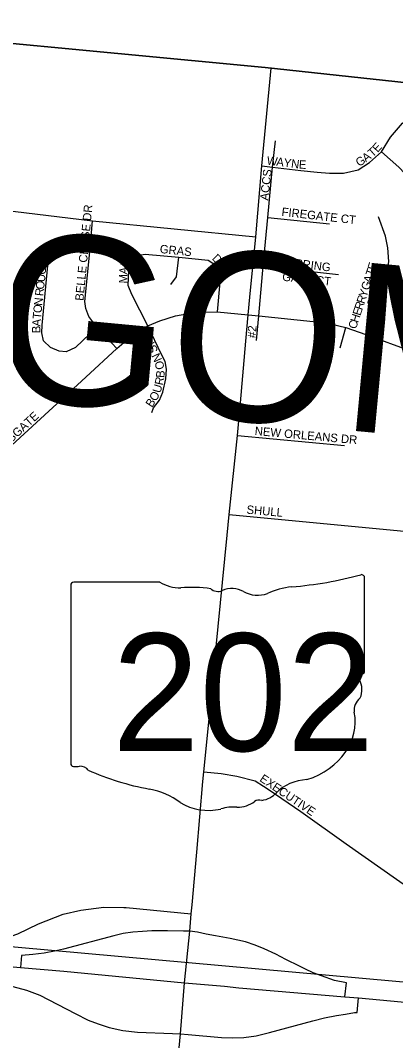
# Model space of a CAD drawing. Extents: x 0 to 680, y 0 to 440.
# Drawn here: x 66.7 to 73.29, y 260.23 to 278.15 of the extents above; entities that cross this region are included whole.
import ezdxf

# ---------------------------------------------------------------- set-up
doc = ezdxf.new("R2010")
doc.units = 0
for name, color, linetype in [('GM_X_Adjacent_County', 7, 'Continuous'), ('GM_X_Adjacent_County_Text', 7, 'Continuous'), ('GM_X_City_Street', 7, 'Continuous'), ('GM_X_City_Street_Text', 7, 'Continuous'), ('GM_X_County', 7, 'Continuous'), ('GM_X_Interchange_Ramps', 7, 'Continuous'), ('GM_X_Interstate_Route', 7, 'Continuous'), ('GM_X_Section', 7, 'Continuous'), ('GM_X_State_Location', 7, 'Continuous'), ('GM_X_State_Route', 7, 'Continuous'), ('GM_X_State_Shield', 7, 'Continuous')]:
    doc.layers.add(name, color=color, linetype=linetype)

msp = doc.modelspace()

# ---------------------------------------------------------------- linework, layer by layer
at = {"layer": 'GM_X_Adjacent_County'}
for points in [[(47.02, 308.647), (47.02, 297.605), (47.136, 296.47), (47.708, 293.469), (47.673, 290.467), (48.191, 288.97), (48.899, 287.478), (50.382, 285.963), (52.043, 282.914), (53.205, 281.417), (53.473, 278.963), (55.844, 278.74), (63.104, 278.067), (70.999, 277.32), (74.792, 276.91), (79.867, 276.361), (80.338, 276.31), (87.389, 275.738), (92.667, 275.254), (94.764, 275.075), (102.624, 274.346)], [(47.02, 308.647), (47.02, 297.605), (47.136, 296.47), (47.708, 293.469), (47.673, 290.467), (48.191, 288.97), (48.899, 287.478), (50.382, 285.963), (52.043, 282.914), (53.205, 281.417), (53.473, 278.963), (55.844, 278.74), (63.104, 278.067), (70.999, 277.32), (74.792, 276.91), (79.867, 276.361), (80.338, 276.31), (87.389, 275.738), (92.667, 275.254), (94.764, 275.075), (102.624, 274.346)], [(102.624, 274.346), (94.764, 275.075), (92.667, 275.254), (87.389, 275.738), (80.338, 276.31), (79.867, 276.361), (74.792, 276.91), (70.999, 277.32), (63.104, 278.067), (55.844, 278.74), (53.473, 278.963), (53.205, 281.417), (52.043, 282.914), (50.382, 285.963), (48.899, 287.478), (48.191, 288.97), (47.673, 290.467), (47.708, 293.469), (47.136, 296.47), (47.02, 297.605), (47.02, 177.346)]]:
    msp.add_lwpolyline(points, dxfattribs=at)
at = {"layer": 'GM_X_City_Street'}
for points in [[(70.942, 275.595), (71.129, 275.57), (71.625, 275.511), (71.91, 275.482), (72.13, 275.465), (72.374, 275.465), (72.629, 275.523), (72.833, 275.65), (73.039, 275.839), (73.202, 276.096), (73.411, 276.346), (73.546, 276.451), (73.759, 276.551), (73.994, 276.598), (74.345, 276.573), (74.765, 276.544), (75.307, 276.485), (75.602, 276.457), (75.803, 276.417), (75.979, 276.347), (76.14, 276.253), (76.351, 276.087)], [(70.843, 272.525), (70.888, 272.958), (70.965, 273.833), (71.047, 274.689), (71.129, 275.57), (71.18, 276.032)], [(73.567, 272.341), (73.894, 273.186), (73.972, 273.481), (74.021, 273.763), (74.033, 274.016), (74.001, 274.339), (73.969, 274.496), (73.935, 274.646), (73.805, 274.948), (73.682, 275.174), (73.55, 275.353), (73.346, 275.573), (73.039, 275.839)], [(62.943, 275.156), (66.171, 274.842), (67.964, 274.631), (70.834, 274.348)], [(68.391, 272.389), (68.041, 272.763), (67.898, 272.949), (67.847, 273.09), (67.833, 273.214), (67.923, 274.14), (67.964, 274.631)], [(71.047, 274.689), (72.131, 274.578)], [(72.764, 272.634), (73.099, 273.556), (73.141, 273.706), (73.171, 273.912), (73.15, 274.157), (73.111, 274.361), (72.991, 274.701)], [(68.041, 272.763), (67.666, 272.403), (67.504, 272.328), (67.379, 272.337), (67.226, 272.402), (67.105, 272.523), (67.075, 272.661), (67.081, 272.799), (67.192, 273.969), (67.242, 274.082), (67.31, 274.14), (67.39, 274.175), (67.568, 274.173), (67.923, 274.14)], [(68.939, 272.782), (68.654, 273.335), (68.591, 273.493), (68.603, 273.762), (68.66, 273.934), (68.781, 274.026), (68.889, 274.045), (69.484, 273.988), (69.994, 273.94), (70.132, 273.851), (70.2, 273.724), (70.2, 273.551), (70.153, 273.03)], [(69.343, 273.509), (69.44, 273.646), (69.484, 273.988)], [(70.965, 273.833), (72.286, 273.688)], [(65.96, 270.156), (67.848, 271.885), (68.391, 272.389), (68.638, 272.596), (68.939, 272.782), (69.149, 272.87), (69.423, 272.959), (69.786, 273.026), (70.153, 273.03), (70.697, 272.98), (70.888, 272.958), (71.841, 272.861), (72.168, 272.811), (72.414, 272.753), (72.764, 272.634), (73.567, 272.341)], [(69.007, 271.263), (69.038, 271.343), (69.141, 271.481), (69.203, 271.622), (69.252, 271.855), (69.264, 272.022), (69.24, 272.157), (69.179, 272.284), (68.939, 272.782)], [(72.316, 272.4), (72.414, 272.753)], [(70.514, 270.86), (72.394, 270.683)], [(70.367, 269.473), (77.802, 268.765), (80.552, 268.499), (83.026, 268.256), (86.292, 267.936), (89.501, 267.603), (91.209, 267.449), (91.849, 267.397), (92.491, 267.422), (93.212, 267.516), (93.58, 267.534), (93.89, 267.521), (96.364, 267.28), (101.905, 266.772)], [(69.918, 264.955), (70.225, 264.923), (70.503, 264.875), (70.824, 264.793), (70.97, 264.702)], [(70.97, 264.702), (71.069, 264.64), (71.627, 264.259), (72.422, 263.69), (73.638, 262.835), (73.974, 262.594), (74.195, 262.441), (74.4, 262.327), (74.588, 262.243), (74.794, 262.167), (75.029, 262.115), (76.124, 262.003), (78.007, 261.823), (80.28, 261.592), (82.742, 261.353), (83.042, 261.335), (83.191, 261.347), (83.483, 261.404), (83.662, 261.414), (84.865, 261.298), (85.497, 261.237)], [(65.053, 262.027), (65.868, 261.958), (66.209, 261.984), (66.419, 262.026), (66.652, 262.111), (67.015, 262.286), (67.451, 262.457), (67.759, 262.527), (68.165, 262.58), (68.515, 262.574), (68.557, 262.571)], [(68.557, 262.571), (69.701, 262.462)]]:
    msp.add_lwpolyline(points, dxfattribs=at)
at = {"layer": 'GM_X_County'}
msp.add_lwpolyline([(102.624, 274.346), (94.764, 275.075), (92.667, 275.254), (87.389, 275.738), (80.338, 276.31), (79.867, 276.361), (74.792, 276.91), (70.999, 277.32), (63.104, 278.067), (55.844, 278.74), (53.473, 278.963), (53.205, 281.417), (52.043, 282.914), (50.382, 285.963), (48.899, 287.478), (48.191, 288.97), (47.673, 290.467), (47.708, 293.469), (47.136, 296.47), (47.02, 297.605), (47.02, 177.346)], dxfattribs=at)
at = {"layer": 'GM_X_Interchange_Ramps'}
for points in [[(69.675, 262.154), (69.566, 262.154), (69.283, 262.16), (69.01, 262.16), (68.844, 262.151), (68.671, 262.137), (68.506, 262.116), (68.342, 262.076), (67.453, 261.839), (67.297, 261.802), (67.115, 261.767), (66.916, 261.744), (66.715, 261.727), (66.703, 261.52)], [(72.397, 261.004), (72.425, 261.248), (72.218, 261.292), (71.985, 261.374), (71.842, 261.427), (71.704, 261.488), (71.6, 261.54), (71.361, 261.66), (71.185, 261.751), (70.983, 261.844), (70.823, 261.908), (70.653, 261.968), (70.385, 262.03), (70.126, 262.076), (69.961, 262.105), (69.808, 262.137), (69.675, 262.154)], [(66.302, 261.556), (66.272, 261.256), (66.563, 261.186), (66.806, 261.118), (67.04, 261.03), (67.663, 260.713), (67.889, 260.591), (68.067, 260.529), (68.26, 260.463), (68.495, 260.411), (68.756, 260.384), (69.371, 260.362), (69.51, 260.355)], [(69.51, 260.355), (69.644, 260.342), (70.229, 260.291), (70.43, 260.281), (70.625, 260.286), (70.84, 260.321), (71.075, 260.375), (71.837, 260.582), (72.04, 260.633), (72.25, 260.675), (72.409, 260.697), (72.57, 260.725), (72.616, 260.729), (72.635, 260.983)]]:
    msp.add_lwpolyline(points, dxfattribs=at)
at = {"layer": 'GM_X_Interstate_Route'}
for points in [[(66.302, 261.556), (66.703, 261.52), (67.459, 261.452), (69.579, 261.251)], [(69.579, 261.251), (70.283, 261.189), (70.538, 261.163), (72.397, 261.004), (72.635, 260.983), (80.379, 260.257), (92.088, 259.16), (97.539, 258.662), (100.447, 258.38)]]:
    msp.add_lwpolyline(points, dxfattribs=at)
at = {"layer": 'GM_X_Section'}
msp.add_lwpolyline([(61.775, 262.316), (77.523, 260.9), (76.108, 245.175), (60.408, 246.656)], close=True, dxfattribs=at)
at = {"layer": 'GM_X_State_Route'}
for points in [[(70.728, 273.288), (70.834, 274.348), (70.942, 275.595), (71.104, 277.31)], [(70.657, 272.515), (70.697, 272.98), (70.728, 273.288)], [(70.563, 271.431), (70.657, 272.515)], [(70.331, 269.112), (70.367, 269.473), (70.514, 270.86), (70.563, 271.431)], [(69.994, 265.711), (70.133, 267.091), (70.331, 269.112)], [(69.903, 264.784), (69.918, 264.955), (69.994, 265.711)], [(69.795, 263.546), (69.903, 264.784)], [(69.715, 262.617), (69.795, 263.546)], [(69.579, 261.251), (69.675, 262.154), (69.701, 262.462), (69.715, 262.617)], [(69.365, 258.81), (69.396, 259.128), (69.51, 260.355), (69.579, 261.251)]]:
    msp.add_lwpolyline(points, dxfattribs=at)
at = {"layer": 'GM_X_State_Shield'}
for p, q in [((72.743, 266.725), (72.743, 268.363)), ((67.584, 268.232), (67.584, 265.099)), ((69.146, 268.286), (67.635, 268.286)), ((72.743, 266.725), (72.743, 266.725))]:
    msp.add_line(p, q, dxfattribs=at)
for centre, major_axis, start_param, end_param in [((70.906, 272.556), (5.471, 0), 4.814394, 5.042369), ((72.686, 268.37), (0.0574, 0), 6.141152, 7.989035), ((67.643, 268.238), (0.0598, 0), 1.712693, 3.28349), ((69.506, 268.649), (0.58, 0), 4.042523, 4.731795), ((69.698, 266.527), (2.081, 0), 1.404758, 1.657858), ((70.17, 268.255), (0.167, 0), 3.836095, 5.185415), ((70.416, 267.893), (0.348, 0), 0.950623, 2.079405), ((71.604, 267.329), (1.101, 0), 1.699011, 2.107814), ((70.865, 268.389), (0.418, 0), 4.081561, 5.145723), ((72.682, 266.718), (0.0615, 0), 5.05454, 6.418171), ((72.73, 266.604), (0.0889, 0), 1.883978, 3.671073), ((72.165, 266.397), (0.534, 0), 5.934695, 6.695948), ((72.949, 266.039), (0.388, 0), 2.387724, 3.262537), ((71.212, 265.83), (1.368, 0), 5.101752, 6.440018), ((67.644, 265.092), (0.0603, 0), 3.00124, 4.508301), ((67.653, 265.413), (0.46, 0), 4.665946, 4.897461), ((67.747, 264.918), (0.166, 0), 0.519207, 1.627899), ((69.842, 267.733), (3.951, 0), 4.195997, 4.488961), ((71.789, 264.22), (0.749, 0), 1.647645, 2.488434), ((68.664, 263.692), (1.236, 0), 0.823519, 1.323587), ((70.84, 264.796), (0.442, 0), 4.937069, 5.64225), ((70.001, 264.903), (0.784, 0), 4.026481, 4.996735), ((70.512, 264.668), (0.418, 0), 4.691044, 5.507374), ((70.89, 264.365), (0.118, 0), 1.147584, 2.315152), ((70.454, 263.82), (0.645, 0), 1.495662, 1.94098)]:
    msp.add_ellipse(centre, major_axis=major_axis, ratio=0.8, start_param=start_param, end_param=end_param, dxfattribs=at)

# ---------------------------------------------------------------- texts
at = {"layer": 'GM_X_Adjacent_County_Text'}
msp.add_text('MONTGOMERY COUNTY', height=2.96462, rotation=354.6312, dxfattribs=at).set_placement((54.51, 272.637))
at = {"layer": 'GM_X_City_Street_Text'}
for s, height, rotation, p in [('T', 0.148, 41.5389, (72.882, 275.738)), ('E', 0.148, 47.6184, (72.972, 275.82)), ('W', 0.148, 352.9042, (71.02, 275.617)), ('A', 0.148, 352.8994, (71.188, 275.597)), ('Y', 0.148, 352.8994, (71.317, 275.58)), ('N', 0.148, 352.8994, (71.447, 275.564)), ('E', 0.148, 356.2163, (71.586, 275.547)), ('G', 0.148, 31.8409, (72.645, 275.574)), ('A', 0.148, 37.0903, (72.768, 275.652)), ('ACCS', 0.1482, 83.6631, (71.053, 274.98)), ('BELLE CHASE DR', 0.14823, 84.5835, (67.805, 273.219)), ('FIREGATE CT', 0.14823, 353.5154, (71.28, 274.717)), ('D', 0.148, 69.3391, (67.165, 273.94)), ('R', 0.148, 52.8193, (67.206, 274.052)), ('D', 0.148, 49.9818, (68.619, 273.902)), ('I', 0.148, 34.0538, (68.694, 273.994)), ('GRAS', 0.1482, 353.9264, (69.141, 274.065)), ('E', 0.148, 84.061, (67.153, 273.807)), ('R', 0.148, 71.9797, (68.59, 273.803)), ('D', 0.148, 316.0355, (70.054, 273.956)), ('R', 0.148, 302.8009, (70.142, 273.872)), ('SPRING', 0.1482, 353.0183, (71.385, 273.83)), ('E', 0.148, 72.5479, (72.932, 273.747)), ('G', 0.148, 84.0654, (67.139, 273.677)), ('A', 0.148, 84.1981, (68.578, 273.681)), ('GATE CT', 0.1482, 354.0936, (71.293, 273.577)), ('T', 0.148, 71.7622, (72.899, 273.646)), ('O', 0.148, 84.0436, (67.112, 273.417)), ('U', 0.148, 84.0786, (67.126, 273.547)), ('M', 0.148, 88.7614, (68.575, 273.528)), ('G', 0.148, 71.7424, (72.817, 273.398)), ('A', 0.148, 71.724, (72.858, 273.522)), ('R', 0.148, 84.0647, (67.1, 273.301)), ('Y', 0.148, 71.724, (72.776, 273.274)), ('CT', 0.1482, 70.5606, (72.915, 273.101)), ('N', 0.148, 84.0786, (67.083, 273.132)), ('R', 0.148, 71.7187, (72.702, 273.051)), ('R', 0.148, 71.7632, (72.739, 273.163)), ('T', 0.148, 84.2241, (67.059, 272.898)), ('O', 0.148, 84.0436, (67.069, 273.002)), ('H', 0.148, 71.7564, (72.629, 272.828)), ('E', 0.148, 71.7464, (72.67, 272.952)), ('A', 0.148, 86.0405, (67.05, 272.77)), ('C', 0.148, 71.7187, (72.592, 272.717)), ('B', 0.148, 89.4171, (67.049, 272.654)), ('#2', 0.1482, 85.9166, (70.832, 272.566)), ('T', 0.148, 114.4507, (69.077, 272.441)), ('S', 0.148, 114.548, (69.121, 272.346)), ('N', 0.148, 114.6465, (69.191, 272.192)), ('O', 0.148, 103.1848, (69.232, 272.034)), ('B', 0.148, 84.9478, (69.225, 271.866)), ('U', 0.148, 73.3814, (69.157, 271.594)), ('R', 0.148, 78.1755, (69.198, 271.733)), ('O', 0.148, 60.7963, (69.08, 271.448)), ('B', 0.148, 56.97, (69.01, 271.34)), ('CHARLESGATE', 0.14823, 42.5803, (65.949, 270.184)), ('NEW ORLEANS DR', 0.14823, 354.8489, (70.81, 270.869)), ('SHULL', 0.1482, 354.923, (70.666, 269.487)), ('EXECUTIVE', 0.1482, 325.9078, (70.888, 264.8))]:
    msp.add_text(s, height=height, rotation=rotation, dxfattribs=at).set_placement(p)
at = {"layer": 'GM_X_State_Location'}
for s in ['s', 'r']:
    msp.add_text(s, height=0.00296, dxfattribs=at).set_placement((70.106, 266.457))
msp.add_text('202', height=0.00296, rotation=0, dxfattribs=at).set_placement((69.059, 266.241))
at = {"layer": 'GM_X_State_Shield'}
msp.add_text('202', height=2.0637, dxfattribs=at).set_placement((68.31, 265.32))

doc.saveas('drawing.dxf')
